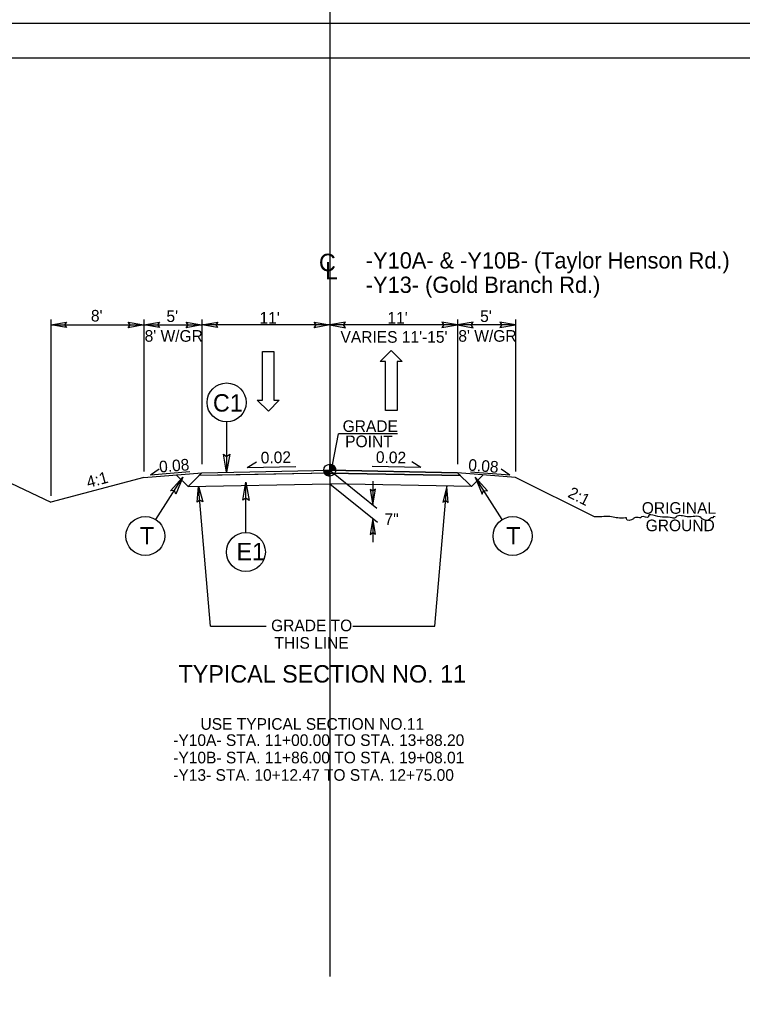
# Model space of a CAD drawing. Extents: x 18938 to 19565, y 6931 to 7973.
# Drawn here: x 19224.8 to 19287.1, y 7287.9 to 7371.6 of the extents above; entities that cross this region are included whole.
import ezdxf

# ---------------------------------------------------------------- set-up
doc = ezdxf.new("R2010")
doc.units = 0
for name, color, linetype in [('Old_Level_11', 7, 'Continuous'), ('Old_Level_2', 7, 'Continuous'), ('Prop Dimension', 7, 'Continuous'), ('Prop Pavement Schedule Description CELL', 7, 'Continuous'), ('Prop Shade Medium', 7, 'Continuous'), ('Prop Terminator CELL', 7, 'Continuous'), ('Sheet Data Field CELL', 7, 'Continuous'), ('Sheet Plot Border Outside CELL', 7, 'Continuous'), ('Sheet Typical CELL', 7, 'Continuous'), ('Typical Curb CELL', 7, 'Continuous'), ('Typical Detail Wedge1 CELL', 7, 'Continuous'), ('Typical Detail Wedge2 CELL', 7, 'Continuous'), ('Typical Detail Wedge3 CELL', 7, 'Continuous'), ('Typical Guardrail CELL', 7, 'Continuous'), ('Typical Hinge Slope Arterial CELL', 7, 'Continuous'), ('Typical Pavement Slope Information CELL', 7, 'Continuous'), ('Typical Shoulder Slope Information CELL', 7, 'Continuous'), ('Typical Terminator CELL', 7, 'Continuous'), ('Typical Text General CELL', 7, 'Continuous'), ('Typical Text Grade Point CELL', 7, 'Continuous'), ('Typical Text ID Circle CELL', 7, 'Continuous'), ('Typical Text Label CELL', 7, 'Continuous')]:
    doc.layers.add(name, color=color, linetype=linetype)

msp = doc.modelspace()

# ---------------------------------------------------------------- linework, layer by layer
at = {"layer": 'Prop Dimension'}
msp.add_lwpolyline([(19155.167, 7224.873), (19382.434, 7224.873), (19382.434, 7371.306), (19155.167, 7371.306)], close=True, dxfattribs=at)
at = {"layer": 'Prop Pavement Schedule Description CELL'}
for p, q in [((19240.522, 7332.62), (19251.522, 7332.84)), ((19262.522, 7332.62), (19251.521, 7332.84)), ((19235.522, 7332.22), (19240.522, 7332.62)), ((19239.331, 7331.429), (19238.317, 7332.443)), ((19239.331, 7331.429), (19240.522, 7332.62)), ((19251.522, 7332.59), (19240.267, 7332.365)), ((19251.522, 7332.59), (19262.777, 7332.365)), ((19267.522, 7332.22), (19262.522, 7332.62)), ((19263.712, 7331.429), (19262.522, 7332.62)), ((19263.712, 7331.429), (19264.726, 7332.443)), ((19274.323, 7328.819), (19267.522, 7332.22)), ((19239.331, 7331.429), (19251.522, 7331.673)), ((19244.022, 7331.527), (19244.022, 7331.523)), ((19263.712, 7331.429), (19251.522, 7331.673)), ((19259.022, 7331.527), (19259.022, 7331.523))]:
    msp.add_line(p, q, dxfattribs=at)
at = {"layer": 'Prop Shade Medium'}
for p in [(19213.788, 7336.64), (19235.522, 7332.22)]:
    msp.add_line(p, (19227.522, 7330.071), dxfattribs=at)
at = {"layer": 'Sheet Data Field CELL'}
for points in [[(19228.872, 7345.112), (19227.522, 7345.345), (19228.879, 7345.585), (19228.707, 7345.345)], [(19234.172, 7345.577), (19235.522, 7345.345), (19234.164, 7345.105), (19234.337, 7345.345)], [(19236.872, 7345.112), (19235.522, 7345.345), (19236.879, 7345.585), (19236.707, 7345.345)], [(19239.172, 7345.577), (19240.522, 7345.345), (19239.164, 7345.105), (19239.337, 7345.345)], [(19241.872, 7345.112), (19240.522, 7345.345), (19241.879, 7345.585), (19241.707, 7345.345)], [(19250.177, 7345.577), (19251.527, 7345.345), (19250.17, 7345.105), (19250.342, 7345.345)], [(19252.877, 7345.577), (19251.527, 7345.345), (19252.885, 7345.105), (19252.712, 7345.345)], [(19261.172, 7345.112), (19262.522, 7345.345), (19261.164, 7345.585), (19261.337, 7345.345)], [(19263.872, 7345.577), (19262.522, 7345.345), (19263.879, 7345.105), (19263.707, 7345.345)], [(19266.172, 7345.112), (19267.522, 7345.345), (19266.164, 7345.585), (19266.337, 7345.345)], [(19240.116, 7330.082), (19240.231, 7331.447), (19240.587, 7330.115), (19240.333, 7330.267)], [(19254.999, 7331.185), (19255.231, 7329.835), (19255.471, 7331.193), (19255.231, 7331.02)], [(19261.723, 7330.056), (19261.609, 7331.421), (19261.252, 7330.089), (19261.506, 7330.24)], [(19255.463, 7327.319), (19255.231, 7328.669), (19254.991, 7327.311), (19255.231, 7327.484)]]:
    msp.add_lwpolyline(points, close=True, dxfattribs=at)
at = {"layer": 'Sheet Typical CELL'}
for p, q in [((19227.522, 7345.805), (19227.522, 7330.64)), ((19227.522, 7345.345), (19235.522, 7345.345)), ((19235.522, 7345.805), (19235.522, 7332.717)), ((19235.522, 7345.345), (19240.522, 7345.345)), ((19240.522, 7345.805), (19240.522, 7333.36)), ((19262.522, 7345.345), (19240.522, 7345.345)), ((19262.522, 7345.805), (19262.522, 7333.36)), ((19267.522, 7345.345), (19262.522, 7345.345)), ((19267.522, 7345.805), (19267.522, 7332.717)), ((19251.522, 7332.84), (19255.577, 7329.555)), ((19241.272, 7319.395), (19240.231, 7331.447)), ((19251.522, 7331.673), (19255.627, 7328.348)), ((19255.231, 7331.879), (19255.231, 7329.835)), ((19260.558, 7319.395), (19261.609, 7331.421)), ((19255.231, 7328.669), (19255.231, 7326.645)), ((19241.272, 7319.395), (19246.038, 7319.395)), ((19253.516, 7319.395), (19260.558, 7319.395))]:
    msp.add_line(p, q, dxfattribs=at)
at = {"layer": 'Typical Curb CELL'}
msp.add_spline([(19284.687, 7328.819), (19284.516, 7328.819), (19284.516, 7328.733), (19284.345, 7328.733), (19284.259, 7328.648), (19283.574, 7328.648), (19283.488, 7328.733), (19282.289, 7328.819), (19281.347, 7328.819), (19281.261, 7328.733), (19281.004, 7328.733), (19279.548, 7328.905), (19278.948, 7328.905), (19278.948, 7328.819), (19278.349, 7328.819), (19278.263, 7328.733), (19278.177, 7328.733), (19277.749, 7328.733), (19277.663, 7328.648), (19277.064, 7328.648), (19277.064, 7328.733), (19276.978, 7328.733), (19275.779, 7328.819), (19274.409, 7328.819), (19274.323, 7328.819)], degree=3, dxfattribs=at)
at = {"layer": 'Typical Detail Wedge1 CELL'}
for p, q in [((19251.01, 7332.84), (19251.522, 7332.84)), ((19251.521, 7332.328), (19251.522, 7332.84)), ((19251.522, 7332.84), (19251.521, 7332.328)), ((19251.522, 7332.84), (19251.522, 7333.352)), ((19252.034, 7332.84), (19251.522, 7332.84))]:
    msp.add_line(p, q, dxfattribs=at)
for points in [[(19251.013, 7332.84), (19251.013, 7332.784)], [(19251.023, 7332.84), (19251.023, 7332.724)], [(19251.033, 7332.84), (19251.033, 7332.686)], [(19251.044, 7332.84), (19251.044, 7332.657)], [(19251.054, 7332.84), (19251.054, 7332.632)], [(19251.064, 7332.84), (19251.064, 7332.61)], [(19251.074, 7332.84), (19251.074, 7332.591)], [(19251.084, 7332.84), (19251.084, 7332.574)], [(19251.095, 7332.84), (19251.095, 7332.558)], [(19251.105, 7332.84), (19251.105, 7332.542)], [(19251.115, 7332.84), (19251.115, 7332.529)], [(19251.125, 7332.84), (19251.125, 7332.516)], [(19251.136, 7332.84), (19251.136, 7332.503)], [(19251.146, 7332.84), (19251.146, 7332.492)], [(19251.156, 7332.84), (19251.156, 7332.481)], [(19251.166, 7332.84), (19251.166, 7332.471)], [(19251.177, 7332.84), (19251.177, 7332.462)], [(19251.187, 7332.84), (19251.187, 7332.453)], [(19251.197, 7332.84), (19251.197, 7332.444)], [(19251.207, 7332.84), (19251.207, 7332.435)], [(19251.218, 7332.84), (19251.218, 7332.428)], [(19251.228, 7332.84), (19251.228, 7332.42)], [(19251.238, 7332.84), (19251.238, 7332.413)], [(19251.248, 7332.84), (19251.248, 7332.407)], [(19251.259, 7332.84), (19251.258, 7332.4)], [(19251.269, 7332.84), (19251.269, 7332.394)], [(19251.279, 7332.84), (19251.279, 7332.389)], [(19251.289, 7332.84), (19251.289, 7332.384)], [(19251.299, 7332.84), (19251.299, 7332.378)], [(19251.31, 7332.84), (19251.309, 7332.374)], [(19251.32, 7332.84), (19251.32, 7332.369)], [(19251.33, 7332.84), (19251.33, 7332.365)], [(19251.34, 7332.84), (19251.34, 7332.361)], [(19251.351, 7332.84), (19251.351, 7332.357)], [(19251.361, 7332.84), (19251.361, 7332.353)], [(19251.371, 7332.84), (19251.371, 7332.35)], [(19251.381, 7332.84), (19251.381, 7332.347)], [(19251.392, 7332.84), (19251.392, 7332.344)], [(19251.402, 7332.84), (19251.402, 7332.342)], [(19251.412, 7332.84), (19251.412, 7332.339)], [(19251.423, 7332.84), (19251.422, 7332.337)], [(19251.433, 7332.84), (19251.433, 7332.336)], [(19251.443, 7332.84), (19251.443, 7332.334)], [(19251.453, 7332.84), (19251.453, 7332.332)], [(19251.463, 7332.84), (19251.463, 7332.331)], [(19251.474, 7332.84), (19251.473, 7332.33)], [(19251.484, 7332.84), (19251.484, 7332.329)], [(19251.494, 7332.84), (19251.494, 7332.329)], [(19251.504, 7332.84), (19251.504, 7332.328)], [(19251.514, 7332.84), (19251.514, 7332.328), (19251.514, 7332.328)], [(19251.527, 7333.352), (19251.527, 7333.352), (19251.527, 7332.84)], [(19251.537, 7333.351), (19251.537, 7332.84)], [(19251.547, 7333.351), (19251.547, 7332.84)], [(19251.558, 7333.35), (19251.557, 7332.84)], [(19251.568, 7333.349), (19251.568, 7332.84)], [(19251.578, 7333.349), (19251.578, 7332.84)], [(19251.588, 7333.347), (19251.588, 7332.84)], [(19251.598, 7333.346), (19251.598, 7332.84)], [(19251.609, 7333.344), (19251.609, 7332.84)], [(19251.619, 7333.342), (19251.619, 7332.84)], [(19251.629, 7333.34), (19251.629, 7332.84)], [(19251.64, 7333.338), (19251.64, 7332.84)], [(19251.65, 7333.336), (19251.65, 7332.84)], [(19251.66, 7333.333), (19251.66, 7332.84)], [(19251.67, 7333.33), (19251.67, 7332.84)], [(19251.681, 7333.327), (19251.681, 7332.84)], [(19251.691, 7333.323), (19251.691, 7332.84)], [(19251.701, 7333.319), (19251.701, 7332.84)], [(19251.711, 7333.315), (19251.711, 7332.84)], [(19251.722, 7333.311), (19251.721, 7332.84)], [(19251.732, 7333.306), (19251.732, 7332.84)], [(19251.742, 7333.302), (19251.742, 7332.84)], [(19251.752, 7333.297), (19251.752, 7332.84)], [(19251.762, 7333.291), (19251.762, 7332.84)], [(19251.773, 7333.286), (19251.772, 7332.84)], [(19251.783, 7333.28), (19251.783, 7332.84)], [(19251.793, 7333.274), (19251.793, 7332.84)], [(19251.803, 7333.267), (19251.803, 7332.84)], [(19251.813, 7333.26), (19251.813, 7332.84)], [(19251.824, 7333.253), (19251.824, 7332.84)], [(19251.834, 7333.245), (19251.834, 7332.84)], [(19251.844, 7333.237), (19251.844, 7332.84)], [(19251.855, 7333.229), (19251.855, 7332.84)], [(19251.865, 7333.219), (19251.865, 7332.839)], [(19251.875, 7333.21), (19251.875, 7332.84)], [(19251.885, 7333.2), (19251.885, 7332.839)], [(19251.896, 7333.19), (19251.896, 7332.839)], [(19251.906, 7333.178), (19251.906, 7332.84)], [(19251.916, 7333.166), (19251.916, 7332.839)], [(19251.926, 7333.153), (19251.926, 7332.839)], [(19251.937, 7333.14), (19251.936, 7332.84)], [(19251.947, 7333.125), (19251.947, 7332.839)], [(19251.957, 7333.109), (19251.957, 7332.839)], [(19251.967, 7333.092), (19251.967, 7332.84)], [(19251.977, 7333.073), (19251.977, 7332.839)], [(19251.988, 7333.052), (19251.987, 7332.839)], [(19251.998, 7333.028), (19251.998, 7332.84)], [(19252.008, 7333), (19252.008, 7332.839)], [(19252.018, 7332.964), (19252.018, 7332.839)], [(19252.029, 7332.912), (19252.029, 7332.84)]]:
    msp.add_lwpolyline(points, dxfattribs=at)
msp.add_circle((19251.522, 7332.84), 0.512, dxfattribs=at)
for start, end in [(179.99048, 269.99048), (359.99048, 89.99048)]:
    msp.add_arc((19251.522, 7332.84), 0.512, start, end, dxfattribs=at)
at = {"layer": 'Typical Detail Wedge3 CELL'}
for p, q in [((19245.729, 7338.858), (19245.729, 7343.058)), ((19245.729, 7343.058), (19246.719, 7343.058)), ((19246.719, 7343.058), (19246.719, 7338.858)), ((19255.875, 7342.187), (19256.805, 7343.132)), ((19256.805, 7343.132), (19257.765, 7342.187)), ((19256.325, 7342.187), (19255.875, 7342.187)), ((19256.325, 7337.987), (19256.325, 7342.187)), ((19257.765, 7342.187), (19257.315, 7342.187)), ((19257.315, 7342.187), (19257.315, 7337.987)), ((19246.239, 7337.913), (19245.279, 7338.858)), ((19245.279, 7338.858), (19245.729, 7338.858)), ((19247.169, 7338.858), (19246.239, 7337.913)), ((19246.719, 7338.858), (19247.169, 7338.858)), ((19257.315, 7337.987), (19256.325, 7337.987))]:
    msp.add_line(p, q, dxfattribs=at)
at = {"layer": 'Typical Guardrail CELL'}
msp.add_line((19251.527, 7635.457), (19251.527, 7289.252), dxfattribs=at)
at = {"layer": 'Typical Hinge Slope Arterial CELL'}
for p, q in [((19240.522, 7332.62), (19251.522, 7332.84)), ((19251.522, 7332.84), (19262.522, 7332.62)), ((19240.267, 7332.365), (19240.522, 7332.62)), ((19242.267, 7332.405), (19240.267, 7332.365)), ((19251.522, 7332.59), (19242.267, 7332.405)), ((19242.267, 7332.405), (19242.267, 7332.405)), ((19262.777, 7332.365), (19251.522, 7332.59)), ((19262.522, 7332.62), (19262.777, 7332.365))]:
    msp.add_line(p, q, dxfattribs=at)
at = {"layer": 'Typical Pavement Slope Information CELL'}
msp.add_lwpolyline([(19380.142, 7368.299), (19177.642, 7368.299), (19177.642, 7227.884), (19380.142, 7227.884)], close=True, dxfattribs=at)
at = {"layer": 'Typical Terminator CELL'}
for p, q in [((19242.645, 7336.993), (19242.645, 7332.662)), ((19236.554, 7328.583), (19238.881, 7332.236)), ((19266.359, 7328.582), (19264.033, 7332.235)), ((19244.303, 7327.466), (19244.303, 7331.798))]:
    msp.add_line(p, q, dxfattribs=at)
for centre in [(19242.645, 7338.669), (19235.654, 7327.169), (19267.26, 7327.168), (19244.303, 7325.791)]:
    msp.add_circle(centre, 1.676, dxfattribs=at)
at = {"layer": 'Typical Text General CELL'}
for points in [[(19242.912, 7334.214), (19242.645, 7332.662), (19242.369, 7334.223), (19242.645, 7334.024)], [(19237.822, 7331.071), (19238.881, 7332.236), (19238.275, 7330.772), (19238.149, 7331.087)], [(19265.092, 7331.07), (19264.033, 7332.235), (19264.638, 7330.771), (19264.765, 7331.086)], [(19244.036, 7330.246), (19244.303, 7331.798), (19244.579, 7330.237), (19244.303, 7330.435)]]:
    msp.add_lwpolyline(points, close=True, dxfattribs=at)
at = {"layer": 'Typical Text Grade Point CELL'}
for p, q in [((19236.089, 7332.44), (19236.842, 7332.96)), ((19244.426, 7333.08), (19245.209, 7333.553)), ((19244.426, 7333.08), (19248.615, 7333.164)), ((19259.37, 7333.08), (19255.181, 7333.164)), ((19259.37, 7333.08), (19258.587, 7333.553)), ((19267.02, 7332.396), (19266.267, 7332.916)), ((19236.089, 7332.44), (19239.475, 7332.711)), ((19267.02, 7332.396), (19263.634, 7332.667))]:
    msp.add_line(p, q, dxfattribs=at)
at = {"layer": 'Typical Text ID Circle CELL'}
for p, q in [((19251.523, 7349.023), (19251.527, 7345.345)), ((19251.527, 7345.345), (19251.522, 7329.103)), ((19251.772, 7333.293), (19252.267, 7335.961)), ((19257.344, 7335.96), (19252.267, 7335.961))]:
    msp.add_line(p, q, dxfattribs=at)

# ---------------------------------------------------------------- texts
at = {"layer": 'Old_Level_11'}
for s, height, p in [('TYPICAL SECTION NO. 11', 1.5, (19238.506, 7314.553)), ('USE TYPICAL SECTION NO.11', 1, (19240.398, 7310.489))]:
    msp.add_text(s, height=height, dxfattribs=at).set_placement(p)
at = {"layer": 'Old_Level_2'}
for s, p in [('ORIGINAL', (19278.38, 7329.083)), ('GROUND', (19278.716, 7327.583))]:
    msp.add_text(s, height=1, dxfattribs=at).set_placement(p)
at = {"layer": 'Prop Terminator CELL'}
for s, p in [('C1', (19241.471, 7337.881)), ('T', (19266.715, 7326.448)), ('E1', (19243.495, 7325.079))]:
    msp.add_text(s, height=1.5, dxfattribs=at).set_placement(p)
msp.add_text('T', height=1.5, rotation=360, dxfattribs=at).set_placement((19235.185, 7326.449))
at = {"layer": 'Sheet Plot Border Outside CELL'}
for s, p in [('GRADE', (19252.633, 7336.129)), ('POINT', (19252.851, 7334.818))]:
    msp.add_text(s, height=1, rotation=0.00004, dxfattribs=at).set_placement(p)
at = {"layer": 'Typical Detail Wedge2 CELL'}
for s, p in [("8'", (19230.968, 7345.635)), ("5'", (19237.468, 7345.595)), ("11'", (19245.483, 7345.46)), ("11'", (19256.488, 7345.46)), ("5'", (19264.468, 7345.595)), ("8' W/GR", (19235.592, 7343.895)), ("VARIES 11'-15'", (19252.449, 7343.809)), ("8' W/GR", (19262.592, 7343.895)), ('7"', (19256.238, 7328.129)), ('GRADE TO', (19246.474, 7318.97)), ('THIS LINE', (19246.765, 7317.47)), ('-Y10A- STA. 11+00.00 TO STA. 13+88.20', (19238.052, 7309.096)), ('-Y10B- STA. 11+86.00 TO STA. 19+08.01', (19238.052, 7307.596)), ('-Y13- STA. 10+12.47 TO STA. 12+75.00          ', (19238.052, 7306.096))]:
    msp.add_text(s, height=1, dxfattribs=at).set_placement(p)
at = {"layer": 'Typical Shoulder Slope Information CELL'}
for s, rotation, p in [('4:1', 15.1346, (19230.737, 7331.296)), ('2:1', 333.43491, (19271.935, 7330.559))]:
    msp.add_text(s, height=1, rotation=rotation, dxfattribs=at).set_placement(p)
at = {"layer": 'Typical Text Grade Point CELL'}
for s, rotation, p in [('0.02', 1.14574, (19245.593, 7333.415)), ('0.02', 358.85426, (19255.485, 7333.469)), ('0.08', 4.5738, (19236.877, 7332.629)), ('0.08', 355.4262, (19263.416, 7332.81))]:
    msp.add_text(s, height=1, rotation=rotation, dxfattribs=at).set_placement(p)
at = {"layer": 'Typical Text Label CELL'}
for s, height, p in [('C', 1.5, (19250.593, 7349.971)), ('-Y10A- & -Y10B- (Taylor Henson Rd.)', 1.4, (19254.631, 7350.199)), ('L', 1.5, (19251.109, 7349.264)), ('-Y13- (Gold Branch Rd.)', 1.4, (19254.631, 7348.099))]:
    msp.add_text(s, height=height, dxfattribs=at).set_placement(p)

doc.saveas('drawing.dxf')
